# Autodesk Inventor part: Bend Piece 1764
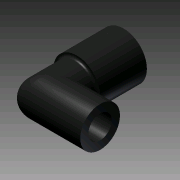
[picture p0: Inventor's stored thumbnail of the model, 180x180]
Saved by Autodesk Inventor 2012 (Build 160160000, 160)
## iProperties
Created: 2010-02
Part Number: Bend Piece 1764
Document SubType Name: Modeling
Designer: jgehrig
Density: 1 g/cm^3
Material: Default
Author: jgehrig
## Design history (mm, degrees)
sketch "Sketch1"
  geometry: C1 r 3.175 at (-15.677, -0.761); C2 r 6.35 at (-15.677, -0.761); 1 further point
  constraints: 2 centre point, 1 coincident
  dimensions: "d0" = 6.35 diameter of C1; "d1" = 12.7 diameter of C2
extrude "Extrusion1" new body sketch "Sketch1" distance "d2" = 12.7; taper "d3" = 0 deg
sketch "Sketch2"
  geometry: C1 r 3.175 at (0, 0) reference; C2 r 6.35 at (0, 0) reference; C3 r 5.397 at (0, 0); 1 further point
  constraints: 1 centre point, 1 coincident
  dimensions: "d4" = 10.795 diameter of C3
extrude "Extrusion2" join sketch "Sketch2" distance "d5" = 12.7; taper "d6" = 0 deg
workplane "Work Plane1"
sketch "Sketch3"
  geometry: L1 (-6.159, 25.4)-(4.636, 25.4) reference; L2 (-6.159, 12.7)-(4.636, 12.7) reference; L3 (4.636, 12.7)-(4.636, 25.4) reference; L4 (-6.159, 12.7)-(-6.159, 25.4) reference; L5 (4.636, 14.605)-(-6.159, 14.605); L6 (4.636, 20.002)-(4.636, 25.4); L7 (-0.761, 25.4)-(4.636, 25.4); L8 (-0.761, 25.4)-(-6.159, 25.4); L9 (-6.159, 25.4)-(-6.159, 20.002); C1 r 3.175 at (-0.761, 20.002); A1 r 5.397 centre (-0.761, 20.002) between (4.636, 20.002) and (-0.761, 25.4); 1 further point
  constraints: 10 end point, 5 tangent, 4 point on line, 3 perpendicular, 3 point on circle, 2 centre point, 1 coincident, 1 collinear, 1 midpoint
  dimensions: "d10" = 6.35 diameter of C1
  node "Projected Loop1"
extrude "Extrusion3" join sketch "Sketch3" distance "d8" = 19.05; taper "d9" = 0 deg
extrude "Extrusion4" cut sketch "Sketch3" stored distance "d11" = 19.05; taper "d12" = 0 deg
workplane "Work Plane2"
sketch "Sketch4"
  geometry: L1 (-21.082, 4.636)-(-2.032, 4.636) reference; L2 (-21.082, 4.636)-(-21.082, -6.159) reference; L3 (-21.082, -6.159)-(-2.032, -6.159) reference; A1 r 5.397 centre (-15.677, -0.761) between (-15.677, 4.636) and (-15.677, -6.159) reference; 1 further point
extrude "Extrusion5" cut sketch "Sketch4" distance "d14" = 12.7; taper "d15" = 0 deg
fillet "Fillet1" dims "d16" = 3.175
fillet "Fillet2" dims "d17" = 0.635
body "Solid1"
other parameters: "d7" = -21.082, "d13" = 25.4
